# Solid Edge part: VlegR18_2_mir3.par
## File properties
Author: Türk
Template: Iso Part.par
Last saved by: Türk
Revision: 2
Application: Solid Edge
Accuracy: 0,990
Username: Türk
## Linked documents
VlegR18_2.par
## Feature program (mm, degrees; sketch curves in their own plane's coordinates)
part copy "CopiedPart_1"
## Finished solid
Body 1: solid body, 154 faces, 385 edges, 214 vertices, 2 internal voids.
  Faces by surface: cylinder 72, torus 31, plane 24, blend 14, cone 8, spun 5
  Edges by curve: circle 176, intersection 113, line 96
Bounding box of the edges (mm; curved faces can reach further): 200.000 x 457.200 x 457.200, from (-100, -228.6, -228.6) to (100, 228.6, 228.6).
Cylindrical faces by radius (mm): R4 x16, R6 x5, R15 x5, R25 x16, R80 x8, R150 x8, R174.2298 x8, R203.6 x2, R216.1 x2, R228.6 x2
Conical faces (half-angle, radius in mm at the cone's reference point): 2.0106 deg R178.4522 x2, 5.4632 deg R201.6202 x2, 54.824 deg R174.2298 x1, 54.824 deg R203.0605 x2, 54.824 deg R203.6 x1
Toroidal faces (ring radius, tube radius in mm): R79 r1 x7, R136.945 r40 x8, R170 r20 x8, R205.6 r2 x2, R214.1 r2 x2, R226.6 r2 x4
Planar faces by outward normal: +x 4, -x 4, oblique 16
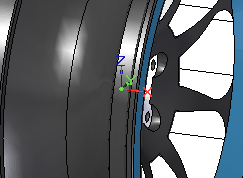
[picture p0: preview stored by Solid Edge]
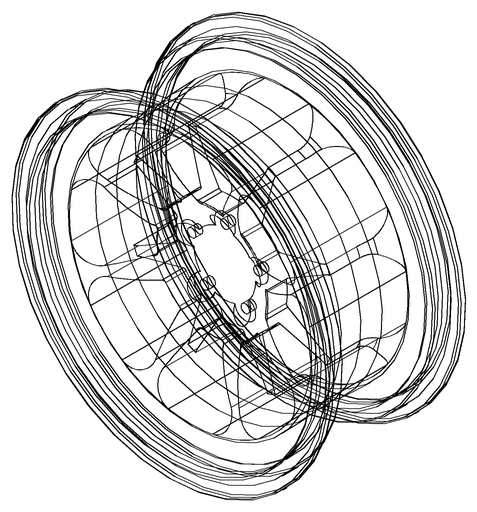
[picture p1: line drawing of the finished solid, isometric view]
